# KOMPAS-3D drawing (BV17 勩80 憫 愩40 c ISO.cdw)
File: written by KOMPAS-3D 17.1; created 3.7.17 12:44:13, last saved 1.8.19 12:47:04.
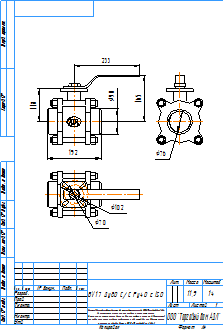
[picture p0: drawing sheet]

Sheet 1: A4, portrait

Title block, sheet 1: name: BV17 Ду80 С/С Ру40 c ISO; material: Сталь 20  ГОСТ 1050-88; mass: 11,9; sheets: 1; sheet format: A4; stored path: C:\Users\kka\KOMPAS_Work\!Trash\СС02 СС03 ФФ Смотровые стекла\СС01.cdw

Views: Спереди 4, Проекционный вид 6
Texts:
  Klimkovich
  ADL
  Рама для чертежей
  Лит-Масса-Масштаб
  Материал-Предприятие
  Масштаб
  Изм.
  Лист
  № докум.
  Подп.
  Дата
  Лит.
  Разраб.
  Пров.
  Т.контр.
  Листов
  Внимание! Данный продукт является объектом авторского права ООО «Торговый Дом АДЛ».
  Запрещается изменение, копирование, распространение
  (в том числе путем копирования на другие сайты и ресурсы в Интернете)
  или любое иное использование информации и объектов без предварительного
  согласия правообладателя (ООО «Торговый Дом АДЛ»).
  Н.контр.
  Утв.
  ООО "Торговый дом АДЛ"
  Изменение
  Номер документа
  Подпись
  Обозначение документа
  Наименование изделия
  Масса изделия по ГОСТ 2.109-73
  Порядковый номер листа
  Общее количество листов в документе
  Характер работы, выполненной лицом, подписавшим документ
  Наименование или индекс предприятия, выпускающего документ
  Инв. № подл.
  Подп. и дата
  Взам. инв. №
  Инв. № дубл.
  Инвентарный номер подлинника по ГОСТ 2.501-68
  Подпись принявшего подлинник в отдел технической документации
  Инвентарный номер подлинника, взамен которого выпущен данный подлинник
  Инвентарный номер дубликата по ГОСТ 2.502-68
  Подпись принявшего дубликат в отдел технической документации
  Справ. №
  Перв. примен.
  Обозначение документа, взамен или на основании которого выпущен данный документ
  Обозначение документа, в котором впервые записан данный документ
  Подпись лица, копировавшего чертеж
  Обозначение формата листа
  !Рама для чертежа
Dimensions and other numbers on the sheet: 192; 118; 233; 165; 90; 76; 1:4; 1; 11,9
